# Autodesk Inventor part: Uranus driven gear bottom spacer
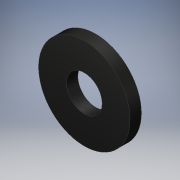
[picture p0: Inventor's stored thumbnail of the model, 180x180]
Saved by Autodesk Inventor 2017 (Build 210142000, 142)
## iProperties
Created: 2016-07
Part Number: Uranus driven gear bottom spacer
Material: Generic
Document SubType Name: Modeling
Designer: Stan
Density: 1 g/cm^3
Appearance: Glossy - Black
Author: Stan
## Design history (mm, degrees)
sketch "Sketch1"
  geometry: C1 r 12.7 at (0, 0); C2 r 4.953 at (0, 0); 1 further point
  constraints: 2 centre point, 2 coincident
  dimensions: "d0" = 25.4 diameter of C1; "d1" = 9.906 diameter of C2
extrude "Extrusion1" new body sketch "Sketch1" distance "d2" = 3.175; taper "d3" = 0 deg
body "Solid1"
